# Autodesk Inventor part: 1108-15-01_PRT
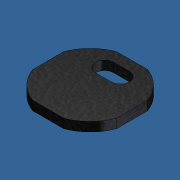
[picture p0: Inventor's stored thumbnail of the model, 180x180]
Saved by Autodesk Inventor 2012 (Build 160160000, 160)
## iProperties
Created: 2007-03
Part Number: 1108-15-01_PRT
Document SubType Name: Modeling
Designer: Andy Moles
Material: ABS Plastic
Mass: 1.09503 g
Surface Area: 10.7786 cm^2
Volume: 1.03305 cm^3
Density: 1.06 g/cm^3
Author: Andy Moles
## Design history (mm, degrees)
workplane "Work Plane1"
sketch "Sketch1"
  geometry: L1 (-2.019, 0.4)-(6.481, 0.4) reference; L2 (-2.019, -4.646)-(-2.019, 0.4) reference; L3 (-2.019, -12.589)-(-2.019, -6.554) reference; L4 (-9.269, 3.12)-(-9.269, -5.32) reference; L5 (6.452, 10.4)-(-1.989, 10.4) reference; L6 (13.731, -5.32)-(13.731, 3.12) reference; L7 (6.481, -12.589)-(6.481, -6.554) reference; L8 (6.481, 0.4)-(6.481, -4.646) reference; L9 (0.081, 2.5)-(4.381, 2.5) reference; L10 (4.381, 7.5)-(0.081, 7.5) reference; L11 (7.481, -9.75)-(7.481, 0.05) reference; L12 (9.181, 1.45)-(9.181, -9.75) reference; L13 (-3.869, 2.3)-(8.331, 2.3) reference; L14 (-4.719, -9.75)-(-4.719, 1.45) reference; L15 (-3.019, 0.05)-(-3.019, -9.75) reference; L16 (6.931, 0.6)-(-2.469, 0.6) reference; L17 (-6.569, 2.497)-(-6.569, -4.697) reference; L18 (5.828, 7.7)-(-1.366, 7.7) reference; L19 (11.031, -4.697)-(11.031, 2.497) reference; L20 (12.731, 2.778)-(12.731, -4.978) reference; L21 (-1.646, 9.4)-(6.109, 9.4) reference; L22 (-8.269, -4.978)-(-8.269, 2.778) reference; L23 (6.481, -12.589)-(-2.019, -12.589); A1 r 1 centre (-1.719, -5.6) between (-2.019, -6.554) and (-2.019, -4.646) reference; A2 r 12.25 centre (2.231, -1.1) between (-9.269, -5.32) and (-2.019, -12.589) reference; A3 r 12.25 centre (2.231, -1.1) between (-1.989, 10.4) and (-9.269, 3.12) reference; A4 r 12.25 centre (2.231, -1.1) between (13.731, 3.12) and (6.452, 10.4) reference; A5 r 12.25 centre (2.231, -1.1) between (6.481, -12.589) and (13.731, -5.32) reference; A6 r 1 centre (6.181, -5.6) between (6.481, -4.646) and (6.481, -6.554) reference; A7 r 2.5 centre (0.081, 5) between (0.081, 7.5) and (0.081, 2.5) reference; A8 r 2.5 centre (4.381, 5) between (4.381, 2.5) and (4.381, 7.5) reference; A9 r 0.55 centre (6.931, 0.05) between (7.481, 0.05) and (6.931, 0.6) reference; A10 r 0.85 centre (8.331, -9.75) between (7.481, -9.75) and (9.181, -9.75) reference; A11 r 0.85 centre (8.331, 1.45) between (9.181, 1.45) and (8.331, 2.3) reference; A12 r 0.85 centre (-3.869, 1.45) between (-3.869, 2.3) and (-4.719, 1.45) reference; A13 r 0.85 centre (-3.869, -9.75) between (-4.719, -9.75) and (-3.019, -9.75) reference; A14 r 0.55 centre (-2.469, 0.05) between (-2.469, 0.6) and (-3.019, 0.05) reference; A15 r 0.55 centre (-6.019, -4.697) between (-6.569, -4.697) and (-6.523, -4.917) reference; A16 r 0.55 centre (-6.019, 2.497) between (-6.523, 2.717) and (-6.569, 2.497) reference; A17 r 9.55 centre (2.231, -1.1) between (-1.585, 7.654) and (-6.523, 2.717) reference; A18 r 0.55 centre (-1.366, 7.15) between (-1.366, 7.7) and (-1.585, 7.654) reference; A19 r 0.55 centre (5.828, 7.15) between (6.048, 7.654) and (5.828, 7.7) reference; A20 r 9.55 centre (2.231, -1.1) between (10.986, 2.717) and (6.048, 7.654) reference; A21 r 0.55 centre (10.481, 2.497) between (11.031, 2.497) and (10.986, 2.717) reference; A22 r 0.55 centre (10.481, -4.697) between (10.986, -4.917) and (11.031, -4.697) reference; A23 r 9.55 centre (2.231, -1.1) between (9.933, -6.747) and (10.986, -4.917) reference; A24 r 0.85 centre (10.618, -7.25) between (9.933, -6.747) and (11.304, -7.753) reference; A25 r 11.25 centre (2.231, -1.1) between (11.304, -7.753) and (12.67, -5.295) reference; A26 r 0.85 centre (11.881, -4.978) between (12.67, -5.295) and (12.731, -4.978) reference; A27 r 0.85 centre (11.881, 2.778) between (12.731, 2.778) and (12.67, 3.095) reference; A28 r 11.25 centre (2.231, -1.1) between (12.67, 3.095) and (6.426, 9.339) reference; A29 r 0.85 centre (6.109, 8.55) between (6.426, 9.339) and (6.109, 9.4) reference; A30 r 0.85 centre (-1.646, 8.55) between (-1.646, 9.4) and (-1.963, 9.339) reference; A31 r 11.25 centre (2.231, -1.1) between (-1.963, 9.339) and (-8.207, 3.095) reference; A32 r 0.85 centre (-7.419, 2.778) between (-8.207, 3.095) and (-8.269, 2.778) reference; A33 r 0.85 centre (-7.419, -4.978) between (-8.269, -4.978) and (-8.207, -5.295) reference; A34 r 11.25 centre (2.231, -1.1) between (-8.207, -5.295) and (-6.761, -7.86) reference; A35 r 0.85 centre (-6.082, -7.349) between (-6.761, -7.86) and (-5.402, -6.838) reference; A36 r 9.55 centre (2.231, -1.1) between (-6.523, -4.917) and (-5.402, -6.838) reference; 2 further points
  constraints: 2 end point, 1 perpendicular
extrude "Extrusion1" new body sketch "Sketch1" distance "d0" = 2.5; taper "d1" = 0 deg
body "Solid1"
node "Projected Loop1"
